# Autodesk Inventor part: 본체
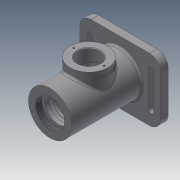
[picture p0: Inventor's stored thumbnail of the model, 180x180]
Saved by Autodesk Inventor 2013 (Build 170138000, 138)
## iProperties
Created: 2021-07
Part Number: 본체
Material: Generic
Document SubType Name: Modeling
Designer: kumcom3
Density: 1 g/cm^3
Author: kumcom3
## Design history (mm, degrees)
sketch "스케치1"
  geometry: C1 r 31 at (0, 0); 1 further point
  constraints: 1 centre point, 1 coincident
  dimensions: "d0" = 62 diameter of C1
extrude "돌출1" new body sketch "스케치1" stored distance "d2" = 115; taper "d3" = 0 deg
node "작업 평면1"
sketch "스케치2"
  geometry: L1 (-58, 45)-(58, 45); L2 (58, 45)-(58, -45); L3 (58, -45)-(-58, -45); L4 (-58, -45)-(-58, 45); C1 r 31 at (0, 0) reference; 3 further points
  constraints: 8 end point, 2 midpoint, 2 parallel, 1 horizontal, 1 horizontal alignment, 1 perpendicular, 1 vertical alignment
  dimensions: "d5" = 116 distance of L1.start L1.end; "d7" = 90 distance of L3.end L1.start
extrude "돌출2" join sketch "스케치2" distance "d8" = 11; taper "d9" = 0 deg
sketch "스케치3"
  geometry: L1 (31, -43.5)-(-31, -43.5) reference; L2 (31, 57.5)-(-31, 57.5) reference; C1 r 27 at (0, 1.5); 2 further points
  constraints: 1 centre point, 1 coincident, 1 midpoint, 1 vertical alignment
  dimensions: "d10" = 54 diameter of C1; "d91" = 56 distance from line of point (0, 1.5) L2
extrude "돌출3" join sketch "스케치3" distance "d12" = 42; taper "d13" = 0 deg
sketch "스케치4"
  geometry: L1 (0, 65.157)-(0, -68.283); L2 (0, 57.5)-(21, 57.5); L3 (21, 57.5)-(21, 48.5); L4 (21, 48.5)-(0, 48.5); L5 (0, 48.5)-(0, 57.5); L6 (0, 48.5)-(24, 48.5); L7 (24, 48.5)-(24, 45.5); L8 (24, 45.5)-(0, 45.5); L9 (0, 45.5)-(0, 48.5); L10 (0, 45.5)-(20, 45.5); L11 (20, 45.5)-(20, 36.5); L12 (20, 36.5)-(0, 36.5); L13 (0, 36.5)-(0, 45.5); L14 (0, 36.5)-(17.5, 36.5); L15 (17.5, 36.5)-(17.5, 20.5); L16 (17.5, 20.5)-(0, 20.5); L17 (0, 20.5)-(0, 36.5); L18 (0, 20.5)-(26, 20.5); L19 (26, 20.5)-(26, -17.5); L20 (26, -17.5)-(0, -17.5); L21 (0, -17.5)-(0, 20.5); L22 (0, -17.5)-(17.5, -17.5); L23 (17.5, -17.5)-(17.5, -28.5); L24 (17.5, -28.5)-(0, -28.5); L25 (0, -28.5)-(0, -17.5); L26 (0, -28.5)-(16, -28.5); L27 (16, -28.5)-(16, -33.5); L28 (16, -33.5)-(0, -33.5); L29 (0, -33.5)-(0, -28.5); L30 (0, -33.5)-(10, -33.5); L31 (10, -33.5)-(10, -36.2); L32 (10, -36.2)-(0, -36.2); L33 (0, -36.2)-(0, -33.5); L34 (0, -36.2)-(12.5, -36.2); L35 (12.5, -36.2)-(12.5, -43.5); L36 (12.5, -43.5)-(0, -43.5); L37 (0, -43.5)-(0, -36.2); L38 (12.5, -43.5)-(16, -43.5); L39 (16, -43.5)-(22, -57.5); L40 (22, -57.5)-(0, -57.5); L41 (31, 57.5)-(-31, 57.5) reference; L42 (-31, -57.5)-(31, -57.5) reference; L43 (0, 33.25)-(18.5, 33.25); L44 (18.5, 33.25)-(18.5, 31.5); L45 (18.5, 31.5)-(0, 31.5); L46 (0, 31.5)-(0, 33.25); L47 (22, -57.5)-(0, -57.5); L48 (0, -43.5)-(0, -57.5); 1 further point
  constraints: 92 end point, 20 parallel, 12 perpendicular, 10 horizontal, 4 collinear, 4 point on line, 1 vertical
  dimensions: "d14" = 9 distance between parallel lines of L4 L41; "d15" = 3 distance between parallel lines of L8 L6; "d16" = 21 distance between parallel lines of L12 L2; "d17" = 38 distance between parallel lines of L20 L18; "d18" = 14 distance between parallel lines of L38 L42; "d19" = 7.3 distance between parallel lines of L36 L34; "d20" = 24 distance between parallel lines of L40 L30; "d21" = 11 distance between parallel lines of L24 L20; "d22" = 65 distance between parallel lines of L26 L12; "d23" = 42 diameter of L3 L1; "d24" = 48 diameter of L7 L1; "d25" = 40 diameter of L11 L13; "d26" = 35 diameter of L15 L17; "d27" = 52 diameter of L19 L1; "d28" = 35 diameter of L23 L1; "d29" = 32 diameter of L27 L1; "d30" = 20 diameter of L31 L33; "d31" = 25 diameter of L35 L1; "d32" = 44 diameter of L39.end L1; "d33" = 32 diameter of L38.end L1; "d34" = 1.75 distance between parallel lines of L45 L43; "d35" = 37 diameter of L44 L1; "d36" = 11 distance between parallel lines of L16 L45
revolve "회전1" sketch "스케치4" stored, may be unused: angle "d37" = 90 deg
sketch "스케치5"
  geometry: L1 (0, 0)-(0, -87.301); L2 (-31, -57.5)-(31, -57.5) reference; L3 (12.5, -43.5)-(-12.5, -43.5) reference; L4 (0, -43.5)-(16, -43.5); L5 (16, -43.5)-(22, -57.5); L6 (22, -57.5)-(0, -57.5); L7 (0, -57.5)-(0, -43.5)
  constraints: 10 end point, 2 collinear, 2 midpoint, 1 point on line, 1 vertical
  dimensions: "d38" = 32 diameter of L4.end L1; "d40" = 44 diameter of L5.end L1
revolve "회전2" sketch "스케치5" stored, may be unused: angle "d41" = 90 deg
sketch "스케치6"
  geometry: L1 (58, -45)-(58, 45) reference; L2 (-48, 25)-(-48, -25); L3 (-40, 25)-(-40, -25); C1 r 31 at (0, 0) reference; A1 r 4 centre (-44, 25) between (-48, 25) and (-40, 25); A2 r 4 centre (-44, -25) between (-48, -25) and (-40, -25); 1 further point
  constraints: 4 end point, 4 point on circle, 3 tangent, 2 centre point, 1 equal radius, 1 horizontal alignment, 1 midpoint, 1 parallel, 1 vertical alignment
  dimensions: "d42" = 8 diameter of A1; "d44" = 44 horizontal distance of C1.centre A1.centre; "d45" = 50 distance of A2.centre A1.centre
extrude "돌출4" cut sketch "스케치6" distance "d46" = 42; taper "d47" = 0 deg
hole "구멍1" diameter "d50" = 32; stored, may be unused: countersink angle "d54" = 90 deg, drill point angle "d56" = 118 deg; dims "d48" = 10, "d49" = 10, "d51" = 6, "d52" = 4, "d53" = 2, "d55" = 20.7
feature "스레드1" dims "d57" = 10, "d58" = 0
fillet "모깎기1" dims "d59" = 3
chamfer "모따기1" distance "d60" = 1; stored, may be unused: second distance "d61" = 2, angle "d62" = 45 deg
fillet "모깎기2" dims "d63" = 0.3
fillet "모깎기3" dims "d64" = 3
fillet "모깎기4" dims "d65" = 0.3
chamfer "모따기2" distance "d66" = 0.7; stored, may be unused: second distance "d67" = 2, angle "d68" = 30 deg
fillet "모깎기5" dims "d69" = 3
chamfer "모따기3" distance "d70" = 1; stored, may be unused: second distance "d71" = 2, angle "d72" = 30 deg
fillet "모깎기6" dims "d73" = 16
fillet "모깎기7" dims "d74" = 3
sketch "스케치7" dims "d75" = 44
  geometry: C1 r 27 at (0, 0) reference; C2 r 17 at (0, 0) reference; 2 further points
  constraints: 2 horizontal alignment, 1 coincident, 2 other
hole "구멍2" sketch "스케치7" at (-22, 0) diameter "d77" = 2.459; stored, may be unused: countersink angle "d81" = 90 deg, drill point angle "d83" = 118 deg; dims "d78" = 6, "d79" = 4, "d80" = 2, "d82" = 8
node "작업 평면2"
sketch "스케치8"
  geometry: L1 (31, 56)-(-31, 56) reference; L2 (42, -27)-(42, 27) reference; 2 further points
  constraints: 1 other
  dimensions: "d87" = 58 distance from line of point (34, -2) L1; "d88" = 8 distance from line of point (34, -2) L2
feature "엠보싱1" sketch "스케치8" dims "d3" = 0, "d89" = 0.5, "d90" = 0
sketch "스케치9"
  geometry: C1 r 31 at (0, 0) reference; C2 r 35 at (0, 0)
  constraints: 1 centre point, 1 coincident
  dimensions: "d92" = 70 diameter of C2
extrude "돌출5" join sketch "스케치9" stored distance "d94" = 0; taper "d95" = 0 deg
node "솔리드1"
mirror "대칭1"
pattern_circular "원형 패턴1" dims angle "d85" = 360 deg
node "투영된 루프1"
node "투영된 루프2"
other parameters: "d4" = -54.5
